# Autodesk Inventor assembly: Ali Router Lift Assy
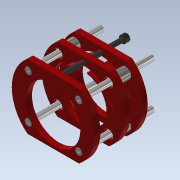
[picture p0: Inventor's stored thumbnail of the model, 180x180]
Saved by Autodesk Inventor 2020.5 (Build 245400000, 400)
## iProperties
Created: 2023-05
Part Number: Ali Router Lift Assy
Project: -
Document SubType Name: Assembly
Designer: A. Bennett
Mass: 574.235 g
Surface Area: 717.274 cm^2
Volume: 145.445 cm^3
Density: 3.94812 g/cm^3
Author: A. Bennett
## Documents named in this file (7)
- C:\CAD_Work\Designs\APR\APR-HYD\HYD\1 Table Saw\Table Saw Assembly\Router Lift\AliEx Router Lift\Ali Router Lift Assy.iam
- C:\CAD_Work\Designs\APR\APR-HYD\HYD\1 Table Saw\Table Saw Assembly\Router Lift\AliEx Router Lift\Post Support Plate.ipt
- C:\CAD_Work\Designs\APR\APR-HYD\HYD\1 Table Saw\Table Saw Assembly\Router Lift\AliEx Router Lift\Corner Post.ipt
- C:\CAD_Work\Designs\APR\APR-HYD\HYD\1 Table Saw\Table Saw Assembly\Router Lift\AliEx Router Lift\Motor mount plate.ipt
- C:\CAD_Work\Designs\APR\APR-HYD\HYD\1 Table Saw\Table Saw Assembly\Router Lift\AliEx Router Lift\Guide Bush.ipt
- C:\CAD_Work\Designs\APR\APR-HYD\HYD\1 Table Saw\Table Saw Assembly\Router Lift\AliEx Router Lift\Jacking Screw.ipt
- C:\CAD_Work\Designs\APR\APR-HYD\HYD\1 Table Saw\Table Saw Assembly\Router Lift\AliEx Router Lift\Post CS Screws.ipt
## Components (16 placed, 6 different names)
1. Post Support Plate:1 — Insert:15, Mate:4, Insert:21, Insert:22, Insert:23, Insert:24, Insert:25, Insert:26, Insert:27
2. Corner Post:1 — Mate:7, Insert:27
3. Corner Post:2 — Mate:4
4. Corner Post:3 — Insert:15
5. Corner Post:4 — Mate:6, Insert:26
6. Motor mount plate:1 — Insert:17, Mate:5
7. Motor mount plate:2 — Insert:16, Insert:18, Insert:19, Insert:20
8. Guide Bush:1 — Insert:18, Mate:5, Mate:7
9. Guide Bush:2 — Insert:20
10. Guide Bush:3 — Insert:16, Insert:17, Mate:6
11. Guide Bush:4 — Insert:19
12. Jacking Screw:1 — Insert:21
13. Post CS Screws:1 — Insert:22
14. Post CS Screws:2 — Insert:25
15. Post CS Screws:3 — Insert:23
16. Post CS Screws:4 — Insert:24
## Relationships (17: Insert 13, Mate 4)
- Insert:15: Post Support Plate:1 ↔ Corner Post:3
- Mate:4: Post Support Plate:1 ↔ Corner Post:2
- Insert:16: Motor mount plate:2 ↔ Guide Bush:3
- Insert:17: Motor mount plate:1 ↔ Guide Bush:3
- Insert:18: Motor mount plate:2 ↔ Guide Bush:1
- Insert:19: Motor mount plate:2 ↔ Guide Bush:4
- Insert:20: Motor mount plate:2 ↔ Guide Bush:2
- Mate:5: Motor mount plate:1 ↔ Guide Bush:1
- Mate:6: Corner Post:4 ↔ Guide Bush:3
- Mate:7: Corner Post:1 ↔ Guide Bush:1
- Insert:21: Post Support Plate:1 ↔ Jacking Screw:1
- Insert:22: Post Support Plate:1 ↔ Post CS Screws:1
- Insert:23: Post Support Plate:1 ↔ Post CS Screws:3
- Insert:24: Post Support Plate:1 ↔ Post CS Screws:4
- Insert:25: Post Support Plate:1 ↔ Post CS Screws:2
- Insert:26: Post Support Plate:1 ↔ Corner Post:4
- Insert:27: Post Support Plate:1 ↔ Corner Post:1
